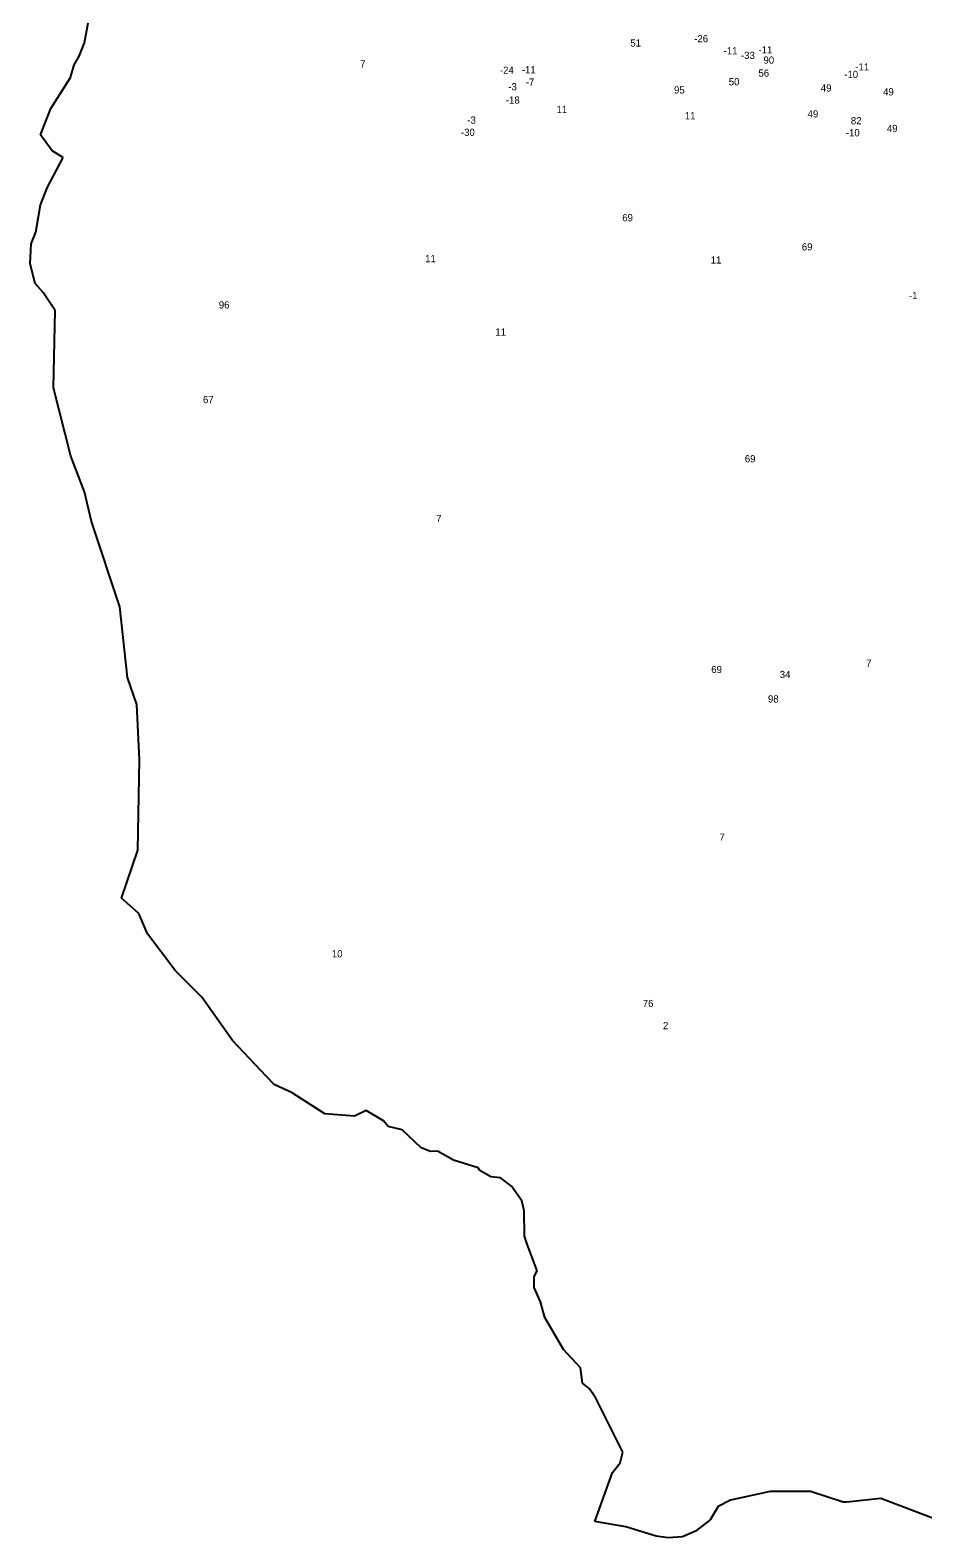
# Model space of a CAD drawing. Extents: x -772472 to -767535, y -969581 to -965387.
# Drawn here: x -772472 to -771228, y -969581 to -967482 of the extents above; entities that cross this region are included whole.
import ezdxf

# ---------------------------------------------------------------- set-up
doc = ezdxf.new("R2010")
doc.units = 0
doc.layers.add('Vrstva 13', color=7, linetype='Continuous')
doc.layers.add('Vrstva 24', color=7, linetype='Continuous')

msp = doc.modelspace()

# ---------------------------------------------------------------- linework, layer by layer
at = {"layer": 'Vrstva 13'}
for p, q in [((-772396.06, -967499.48), (-772391.09, -967471.44)), ((-772403.75, -967518.02), (-772396.06, -967499.48)), ((-772415.5, -967547.41), (-772410.53, -967529.78)), ((-772410.53, -967529.78), (-772403.75, -967518.02)), ((-772443.08, -967590.83), (-772415.5, -967547.41)), ((-772457.32, -967627.26), (-772443.08, -967590.83)), ((-772441.05, -967649.87), (-772457.32, -967627.26)), ((-772447.7, -967700.18), (-772425.78, -967659.25)), ((-772425.78, -967659.25), (-772441.05, -967649.87)), ((-772457.42, -967724.83), (-772447.7, -967700.18)), ((-772463.98, -967762.82), (-772457.42, -967724.83)), ((-772470.54, -967779.1), (-772463.98, -967762.82)), ((-772471.9, -967806.92), (-772470.54, -967779.1)), ((-772465.11, -967834.28), (-772471.9, -967806.92)), ((-772453.59, -967847.17), (-772465.11, -967834.28)), ((-772437.19, -967872.16), (-772453.59, -967847.17)), ((-772439.45, -967979.8), (-772437.19, -967872.16)), ((-772415.04, -968074.78), (-772439.45, -967979.8)), ((-772396.05, -968124.53), (-772415.04, -968074.78)), ((-772386.56, -968165.69), (-772396.05, -968124.53)), ((-772346.77, -968284.64), (-772386.56, -968165.69)), ((-772336.37, -968383.23), (-772346.77, -968284.64)), ((-772323.26, -968420.77), (-772336.37, -968383.23)), ((-772319.31, -968497.55), (-772323.26, -968420.77)), ((-772321.8, -968623.5), (-772319.31, -968497.55)), ((-772344.62, -968690.22), (-772321.8, -968623.5)), ((-772320.66, -968711.7), (-772344.62, -968690.22)), ((-772308.23, -968739.97), (-772320.66, -968711.7)), ((-772270.03, -968791.08), (-772308.23, -968739.97)), ((-772232.5, -968828.16), (-772270.03, -968791.08)), ((-772190.02, -968888.54), (-772232.5, -968828.16)), ((-772142.32, -968938.74), (-772190.02, -968888.54)), ((-772131.7, -968949.82), (-772142.32, -968938.74)), ((-772106.6, -968961.35), (-772131.7, -968949.82)), ((-772061.17, -968990.75), (-772106.6, -968961.35)), ((-772019.8, -968994.14), (-772061.17, -968990.75)), ((-772003.76, -968986.22), (-772019.8, -968994.14)), ((-771979.34, -969000.46), (-772003.76, -968986.22)), ((-771973.01, -969008.15), (-771979.34, -969000.46)), ((-771953.57, -969013.13), (-771973.01, -969008.15)), ((-771926.9, -969038), (-771953.57, -969013.13)), ((-771913.79, -969042.98), (-771926.9, -969038)), ((-771904.07, -969042.52), (-771913.79, -969042.98)), ((-771882.14, -969054.96), (-771904.07, -969042.52)), ((-771847.55, -969066.04), (-771882.14, -969054.96)), ((-771845.06, -969069.44), (-771847.55, -969066.04)), ((-771829.91, -969078.49), (-771845.06, -969069.44)), ((-771816.35, -969079.62), (-771829.91, -969078.49)), ((-771800.98, -969091.38), (-771816.35, -969079.62)), ((-771786.51, -969111.96), (-771800.98, -969091.38)), ((-771783.57, -969125.53), (-771786.51, -969111.96)), ((-771783.12, -969161.03), (-771783.57, -969125.53)), ((-771779.28, -969172.11), (-771783.12, -969161.03)), ((-771765.49, -969209.2), (-771779.28, -969172.11)), ((-771769.33, -969217.11), (-771765.49, -969209.2)), ((-771769.33, -969232.49), (-771769.33, -969217.11)), ((-771760.52, -969252.39), (-771769.33, -969232.49)), ((-771754.64, -969274.32), (-771760.52, -969252.39)), ((-771728.63, -969318.87), (-771754.64, -969274.32)), ((-771704.96, -969344.14), (-771728.63, -969318.87)), ((-771702.02, -969365.51), (-771704.96, -969344.14)), ((-771692.86, -969373.32), (-771702.02, -969365.51)), ((-771683.86, -969385.69), (-771692.86, -969373.32)), ((-771645.88, -969461.67), (-771683.86, -969385.69)), ((-771649.5, -969476.6), (-771645.88, -969461.67)), ((-771660.35, -969490.17), (-771649.5, -969476.6)), ((-771685.22, -969558.46), (-771660.35, -969490.17)), ((-771440.63, -969516.4), (-771495.78, -969528.61)), ((-771384.57, -969516.4), (-771440.63, -969516.4)), ((-771338.9, -969531.32), (-771384.57, -969516.4)), ((-771286.45, -969526.35), (-771333.93, -969531.32)), ((-771149.02, -969578.36), (-771286.45, -969526.35)), ((-771512.96, -969537.65), (-771524.26, -969556.2)), ((-771495.78, -969528.61), (-771512.96, -969537.65)), ((-771333.93, -969531.32), (-771338.9, -969531.32)), ((-771641.81, -969565.7), (-771685.22, -969558.46)), ((-771599.32, -969578.81), (-771641.81, -969565.7)), ((-771524.26, -969556.2), (-771544.61, -969571.57)), ((-771583.04, -969581.07), (-771599.32, -969578.81)), ((-771562.69, -969579.72), (-771583.04, -969581.07)), ((-771544.61, -969571.57), (-771562.69, -969579.72))]:
    msp.add_line(p, q, dxfattribs=at)

# ---------------------------------------------------------------- texts
at = {"layer": 'Vrstva 24'}
for s, p in [('-26', (-771546.514, -967498.51)), ('51', (-771635.541, -967504.62)), ('-11', (-771505.479, -967515.34)), ('-33', (-771481.35, -967521.77)), ('-11', (-771457.009, -967514.21)), ('7', (-772012.126, -967533.75)), ('-24', (-771817.336, -967542.45)), ('-11', (-771786.669, -967541.82)), ('90', (-771449.98, -967528.36)), ('-11', (-771322.059, -967537.88)), ('-7', (-771781.269, -967558.95)), ('50', (-771498.366, -967558.48)), ('56', (-771457.03, -967546.49)), ('-10', (-771337.455, -967548.33)), ('-18', (-771808.984, -967584.05)), ('-3', (-771805.6, -967565.49)), ('95', (-771574.7, -967569.95)), ('49', (-771370.086, -967567.24)), ('49', (-771283.376, -967572.57)), ('11', (-771738.436, -967597.06)), ('11', (-771559.656, -967605.81)), ('49', (-771388.546, -967603.26)), ('-3', (-771862.66, -967611.93)), ('82', (-771328.266, -967612.73)), ('49', (-771278.046, -967623.61)), ('-30', (-771871.55, -967628.94)), ('-10', (-771335.205, -967629.51)), ('69', (-771646.784, -967747.84)), ('69', (-771396.584, -967788.43)), ('11', (-771921.446, -967804.82)), ('11', (-771523.566, -967806.66)), ('-1', (-771247.274, -967856.22)), ('96', (-772208.954, -967869.28)), ('11', (-771823.596, -967907.09)), ('67', (-772231.058, -968001.15)), ('69', (-771476.034, -968083.54)), ('7', (-771906.106, -968166.76)), ('69', (-771522.804, -968376.95)), ('7', (-771307.026, -968368.25)), ('34', (-771427.262, -968383.83)), ('98', (-771443.83, -968417.92)), ('7', (-771511.356, -968610.34)), ('10', (-772051.511, -968772.69)), ('76', (-771618.248, -968841.99)), ('2', (-771590.056, -968872.84))]:
    msp.add_text(s, height=10, dxfattribs=at).set_placement(p)

doc.saveas('drawing.dxf')
